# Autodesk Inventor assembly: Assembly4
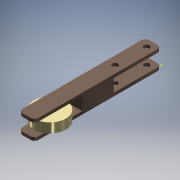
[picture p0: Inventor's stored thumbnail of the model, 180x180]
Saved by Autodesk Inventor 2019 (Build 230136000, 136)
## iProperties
Created: 2019-01
Part Number: Assembly4
Document SubType Name: Assembly
Designer: Patel Family
Author: Patel Family
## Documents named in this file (3)
- A:\Documents\Inventor Files\Assembly4.iam
- A:\Documents\Part41.ipt
- A:\Documents\Part42.ipt
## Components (2 placed, 2 different names)
1. Part41:2
2. Part42:2
## Named parameters: d1_d0 = 0
